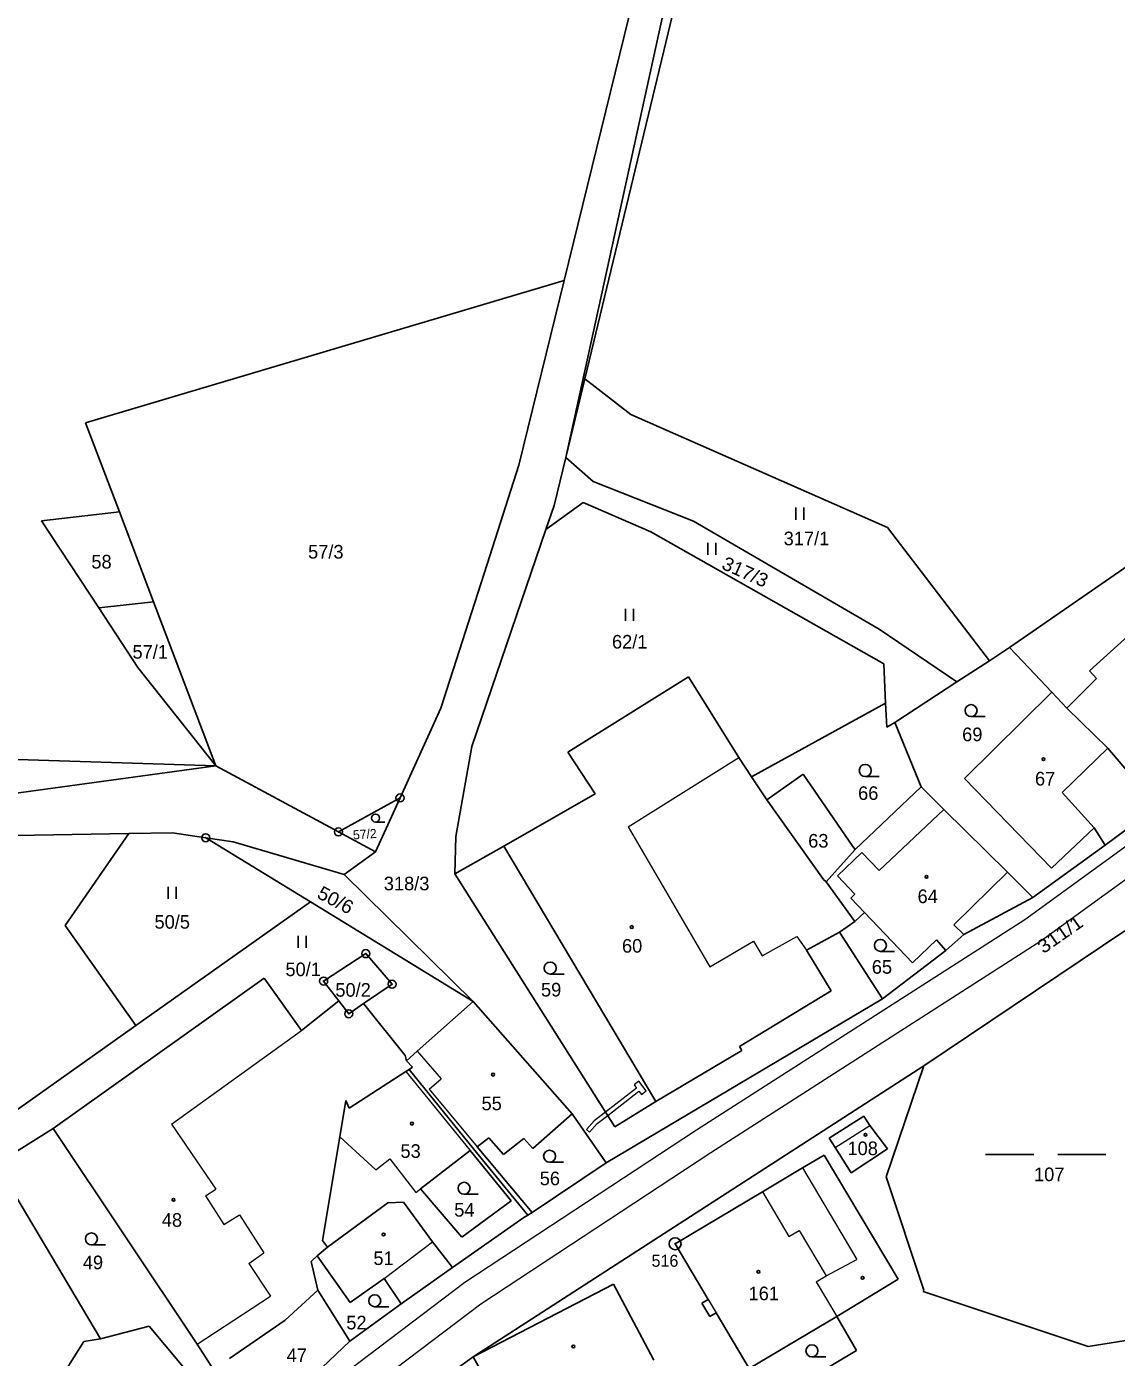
# Model space of a CAD drawing. Extents: x -633485 to -630509, y -1112692 to -1108818.
# Drawn here: x -631971.2 to -631835.2, y -1111718.1 to -1111552 of the extents above; entities that cross this region are included whole.
import ezdxf
from ezdxf.enums import TextEntityAlignment as Align

# ---------------------------------------------------------------- set-up
doc = ezdxf.new("R2010")
doc.units = 0
doc.header["$LTSCALE"] = 0.68
for name, color, linetype, lineweight in [('1', 7, 'Continuous', 25), ('13', 7, 'Continuous', 13), ('3', 7, 'Continuous', 25), ('4', 7, 'Continuous', 13), ('5', 7, 'Continuous', 25), ('8', 7, 'Continuous', 25)]:
    doc.layers.add(name, color=color, linetype=linetype, lineweight=lineweight)
doc.layers.add('2', color=7, linetype='Continuous')

msp = doc.modelspace()

# ---------------------------------------------------------------- linework, layer by layer
at = {"layer": '1'}
for p, q in [((-631901.53, -1111595.94), (-631843.85, -1111356.21)), ((-631904.1, -1111583.66), (-631892.04, -1111534.6)), ((-631903.91, -1111605.76), (-631890.19, -1111543.34)), ((-631963.83, -1111601.41), (-631904.1, -1111583.66)), ((-631909.75, -1111606.69), (-631904.1, -1111583.66)), ((-631903.91, -1111605.76), (-631901.53, -1111595.94)), ((-631901.53, -1111595.94), (-631895.78, -1111600.39)), ((-631895.78, -1111600.39), (-631863.75, -1111614.5)), ((-631963.83, -1111601.41), (-631959.6, -1111612.53)), ((-631905.36, -1111611.74), (-631903.91, -1111605.76)), ((-631903.91, -1111605.76), (-631900.48, -1111608.75)), ((-631913.72, -1111619.07), (-631909.75, -1111606.69)), ((-631900.48, -1111608.75), (-631887.96, -1111613.7)), ((-631848.51, -1111629.48), (-631819.16, -1111609.13)), ((-631969.34, -1111613.67), (-631959.6, -1111612.53)), ((-631959.6, -1111612.53), (-631955.34, -1111623.76)), ((-631906.38, -1111614.73), (-631901.71, -1111611.37)), ((-631906.38, -1111614.73), (-631905.36, -1111611.74)), ((-631901.71, -1111611.37), (-631893.28, -1111615.02)), ((-631969.34, -1111613.67), (-631962.2, -1111624.53)), ((-631887.96, -1111613.7), (-631864.8, -1111627.19)), ((-631915.61, -1111641.81), (-631906.38, -1111614.73)), ((-631893.28, -1111615.02), (-631864.21, -1111631.48)), ((-631863.75, -1111614.5), (-631851.01, -1111631.11)), ((-631919.48, -1111637.05), (-631913.72, -1111619.07)), ((-631962.2, -1111624.53), (-631955.34, -1111623.76)), ((-631955.34, -1111623.76), (-631947.56, -1111644.22)), ((-631962.2, -1111624.53), (-631957.33, -1111631.94)), ((-631855.07, -1111633.76), (-631864.8, -1111627.19)), ((-631851.01, -1111631.11), (-631848.51, -1111629.48)), ((-631848.51, -1111629.48), (-631846.09, -1111632.02)), ((-631957.33, -1111631.94), (-631947.56, -1111644.22)), ((-631864.21, -1111631.48), (-631864.01, -1111636.42)), ((-631855.07, -1111633.76), (-631851.01, -1111631.11)), ((-631846.09, -1111632.02), (-631843.21, -1111635.05)), ((-631903.66, -1111642.54), (-631888.57, -1111633.13)), ((-631888.57, -1111633.13), (-631882.28, -1111643.21)), ((-631862.83, -1111638.83), (-631855.07, -1111633.76)), ((-631854.12, -1111645.8), (-631843.21, -1111635.05)), ((-631843.21, -1111635.05), (-631841.34, -1111637.03)), ((-631924.59, -1111648.24), (-631919.48, -1111637.05)), ((-631880.7, -1111645.61), (-631864.01, -1111636.42)), ((-631864.01, -1111636.42), (-631863.82, -1111639.39)), ((-631841.34, -1111637.03), (-631836.24, -1111642.02)), ((-631863.82, -1111639.39), (-631862.83, -1111638.83)), ((-631862.83, -1111638.83), (-631859.52, -1111646.87)), ((-632001.91, -1111642.47), (-631947.56, -1111644.22)), ((-631917.62, -1111653.03), (-631915.61, -1111641.81)), ((-631903.66, -1111642.54), (-631900.21, -1111647.74)), ((-631836.24, -1111642.02), (-631832.24, -1111646.74)), ((-632001.49, -1111651.65), (-631947.56, -1111644.22)), ((-631947.56, -1111644.22), (-631932.27, -1111652.47)), ((-631882.28, -1111643.21), (-631880.7, -1111645.61)), ((-631880.7, -1111645.61), (-631878.81, -1111648.48)), ((-631878.81, -1111648.48), (-631874.25, -1111645.28)), ((-631874.25, -1111645.28), (-631868.07, -1111654.28)), ((-631854.12, -1111645.8), (-631843.25, -1111657)), ((-631867.79, -1111654.69), (-631859.52, -1111646.87)), ((-631859.52, -1111646.87), (-631856.69, -1111649.68)), ((-631932.27, -1111652.47), (-631924.59, -1111648.24)), ((-631927.66, -1111654.96), (-631924.59, -1111648.24)), ((-631911.64, -1111654.24), (-631900.21, -1111647.74)), ((-631878.81, -1111648.48), (-631871.74, -1111658.4)), ((-631856.69, -1111649.68), (-631848.78, -1111657.52)), ((-631836.57, -1111654.15), (-631830.18, -1111649.38)), ((-632000.57, -1111653.43), (-631958.43, -1111652.69)), ((-631966.4, -1111664.15), (-631958.43, -1111652.69)), ((-631958.43, -1111652.69), (-631952.97, -1111652.59)), ((-631952.97, -1111652.59), (-631948.84, -1111653.21)), ((-631932.27, -1111652.47), (-631927.66, -1111654.96)), ((-631843.25, -1111657), (-631837.93, -1111651.98)), ((-631837.93, -1111651.98), (-631836.57, -1111654.15)), ((-631935.78, -1111661.21), (-631948.84, -1111653.21)), ((-631948.84, -1111653.21), (-631945.4, -1111653.73)), ((-631945.4, -1111653.73), (-631931.58, -1111657.81)), ((-631917.74, -1111657.71), (-631917.62, -1111653.03)), ((-631917.74, -1111657.71), (-631911.64, -1111654.24)), ((-631911.64, -1111654.24), (-631892.66, -1111686.11)), ((-631868.07, -1111654.28), (-631867.79, -1111654.69)), ((-631845.59, -1111660.65), (-631836.57, -1111654.15)), ((-631931.58, -1111657.81), (-631927.66, -1111654.96)), ((-631871.39, -1111658.71), (-631867.79, -1111654.69)), ((-631848.78, -1111657.52), (-631845.59, -1111660.65)), ((-631931.58, -1111657.81), (-631915.46, -1111673.65)), ((-631917.74, -1111657.71), (-631900.34, -1111685.21)), ((-631871.74, -1111658.4), (-631871.39, -1111658.71)), ((-631871.39, -1111658.71), (-631867.81, -1111663.67)), ((-631854.23, -1111665.3), (-631845.59, -1111660.65)), ((-631935.78, -1111661.21), (-631957.55, -1111676.64)), ((-631915.46, -1111673.65), (-631935.78, -1111661.21)), ((-631867.81, -1111663.67), (-631866.6, -1111662.53)), ((-631866.6, -1111662.53), (-631860.64, -1111668.8)), ((-631957.55, -1111676.64), (-631966.4, -1111664.15)), ((-631869.75, -1111665), (-631867.81, -1111663.67)), ((-631873.85, -1111667.25), (-631869.75, -1111665)), ((-631869.75, -1111665), (-631864.38, -1111673.32)), ((-631860.64, -1111668.8), (-631857.63, -1111665.94)), ((-631859.21, -1111681.69), (-631834.1, -1111664.82)), ((-631857.63, -1111665.94), (-631856.44, -1111667.27)), ((-631856.44, -1111667.27), (-631854.23, -1111665.3)), ((-631873.85, -1111667.25), (-631870.79, -1111672.3)), ((-631864.38, -1111673.32), (-631856.44, -1111667.27)), ((-631934.12, -1111671.1), (-631928.87, -1111667.67)), ((-631928.87, -1111667.67), (-631925.58, -1111671.48)), ((-631967.87, -1111689.47), (-631941.54, -1111670.72)), ((-631941.54, -1111670.72), (-631936.89, -1111677.28)), ((-631934.12, -1111671.1), (-631932.21, -1111673.57)), ((-631929.13, -1111673.91), (-631925.58, -1111671.48)), ((-631882.23, -1111679.27), (-631870.79, -1111672.3)), ((-631936.89, -1111677.28), (-631932.21, -1111673.57)), ((-631932.21, -1111673.57), (-631930.98, -1111675.17)), ((-631930.98, -1111675.17), (-631929.13, -1111673.91)), ((-631929.13, -1111673.91), (-631923.96, -1111680.39)), ((-631922.43, -1111679.85), (-631915.46, -1111673.65)), ((-631915.46, -1111673.65), (-631903.08, -1111687.64)), ((-631898.86, -1111693.79), (-631864.38, -1111673.32)), ((-631957.55, -1111676.64), (-631977.11, -1111690.5)), ((-631882.23, -1111679.27), (-631881.94, -1111679.76)), ((-631923.96, -1111680.39), (-631923.77, -1111681.04)), ((-631923.77, -1111681.04), (-631922.43, -1111679.85)), ((-631892.66, -1111686.11), (-631881.94, -1111679.76)), ((-631930.95, -1111686.95), (-631923.85, -1111682.38)), ((-631923.85, -1111682.38), (-631923.44, -1111682.11)), ((-631923.77, -1111681.04), (-631923.02, -1111681.85)), ((-631923.44, -1111682.11), (-631923.02, -1111681.85)), ((-631923.44, -1111682.11), (-631915.43, -1111692.02)), ((-631915.46, -1111717.97), (-631859.21, -1111681.69)), ((-631863.89, -1111695.51), (-631859.21, -1111681.69)), ((-631900.34, -1111685.21), (-631897.77, -1111689.28)), ((-631932.12, -1111690.55), (-631931.36, -1111686.01)), ((-631931.36, -1111686.01), (-631930.95, -1111686.95)), ((-631897.77, -1111689.28), (-631892.66, -1111686.11)), ((-631908.01, -1111692), (-631903.08, -1111687.64)), ((-631903.08, -1111687.64), (-631898.86, -1111693.79)), ((-631871.01, -1111690.69), (-631866.68, -1111687.95)), ((-631866.68, -1111687.95), (-631865.94, -1111689.1)), ((-631865.94, -1111689.1), (-631863.73, -1111692.02)), ((-631974.95, -1111693.92), (-631967.87, -1111689.47)), ((-631967.87, -1111689.47), (-631949.92, -1111716.39)), ((-631934.27, -1111703.46), (-631932.12, -1111690.55)), ((-631914.97, -1111691.79), (-631913.51, -1111690.67)), ((-631913.51, -1111690.67), (-631911.69, -1111692.72)), ((-631911.69, -1111692.72), (-631909.14, -1111690.73)), ((-631909.14, -1111690.73), (-631908.01, -1111692)), ((-631871.01, -1111690.69), (-631870.28, -1111691.86)), ((-631922.02, -1111697.02), (-631915.83, -1111692.23)), ((-631915.83, -1111692.23), (-631910.71, -1111698.51)), ((-631915.43, -1111692.02), (-631908.64, -1111700.3)), ((-631914.97, -1111691.79), (-631908.09, -1111699.96)), ((-631870.28, -1111691.86), (-631868.26, -1111695.04)), ((-631868.26, -1111695.04), (-631863.73, -1111692.02)), ((-631974.95, -1111693.92), (-631965, -1111710.64)), ((-631908.09, -1111699.96), (-631898.86, -1111693.79)), ((-631874.35, -1111694.41), (-631871.64, -1111692.8)), ((-631871.64, -1111692.8), (-631862.42, -1111708.31)), ((-631879.35, -1111697.38), (-631874.35, -1111694.41)), ((-631863.89, -1111695.51), (-631859.2, -1111709.66)), ((-631922.02, -1111697.02), (-631916.88, -1111703.05)), ((-631890.26, -1111703.87), (-631879.35, -1111697.38)), ((-631933.63, -1111704.28), (-631926.11, -1111698.75)), ((-631926.11, -1111698.75), (-631924.17, -1111698.69)), ((-631924.17, -1111698.69), (-631920.53, -1111703.63)), ((-631916.88, -1111703.05), (-631910.71, -1111698.51)), ((-631918.02, -1111706.84), (-631909.13, -1111700.61)), ((-631909.13, -1111700.61), (-631908.64, -1111700.3)), ((-631908.64, -1111700.3), (-631908.09, -1111699.96)), ((-631934.27, -1111703.46), (-631933.63, -1111704.28)), ((-631920.53, -1111703.63), (-631918.02, -1111706.84)), ((-631890.26, -1111703.87), (-631886.13, -1111710.83)), ((-631935.67, -1111706.08), (-631934.91, -1111705.39)), ((-631934.91, -1111705.39), (-631933.63, -1111704.28)), ((-631934.91, -1111705.39), (-631930.8, -1111711.2)), ((-631935.67, -1111706.08), (-631934.84, -1111709.67)), ((-631924.44, -1111711.38), (-631918.02, -1111706.84)), ((-631930.8, -1111711.2), (-631926.55, -1111708.23)), ((-631926.55, -1111708.23), (-631924.44, -1111711.38)), ((-631915.46, -1111717.97), (-631897.93, -1111708.91)), ((-631897.93, -1111708.91), (-631892.89, -1111718.42)), ((-631870.08, -1111712.97), (-631862.42, -1111708.31)), ((-631965, -1111710.64), (-631961.97, -1111715.74)), ((-631938.92, -1111713.4), (-631934.84, -1111709.67)), ((-631934.84, -1111709.67), (-631930.86, -1111716.02)), ((-631859.29, -1111709.82), (-631859.2, -1111709.66)), ((-631859.29, -1111709.82), (-631838.71, -1111716.69)), ((-631930.86, -1111716.02), (-631924.44, -1111711.38)), ((-631886.9, -1111711.29), (-631886.13, -1111710.83)), ((-631886.9, -1111711.29), (-631885.92, -1111712.96)), ((-631945.88, -1111718.19), (-631938.92, -1111713.4)), ((-631885.92, -1111712.96), (-631885.14, -1111712.49)), ((-631885.14, -1111712.49), (-631881.01, -1111719.45)), ((-631881.01, -1111719.45), (-631870.08, -1111712.97)), ((-631870.08, -1111712.97), (-631867.59, -1111717.18)), ((-631964.04, -1111716.07), (-631961.97, -1111715.74)), ((-631961.97, -1111715.74), (-631955.91, -1111714.17)), ((-631955.91, -1111714.17), (-631949.96, -1111721.29)), ((-631838.71, -1111716.69), (-631832.42, -1111715.71)), ((-631974.18, -1111732.05), (-631964.04, -1111716.07)), ((-631949.92, -1111716.39), (-631947.83, -1111719.66)), ((-631939.82, -1111724.55), (-631930.86, -1111716.02)), ((-631878.44, -1111723.62), (-631867.59, -1111717.18)), ((-631917.89, -1111719.74), (-631915.46, -1111717.97)), ((-631915.46, -1111717.97), (-631911.4, -1111725.24))]:
    msp.add_line(p, q, dxfattribs=at)
at = {"layer": '13'}
msp.add_lwpolyline([(-631935.9, -1111727.56), (-631914.51, -1111711.36), (-631885.8, -1111692.49), (-631844.62, -1111666.09), (-631807.03, -1111638.81), (-631767.97, -1111614.41), (-631746.51, -1111599.55), (-631748.39, -1111596.83), (-631769.96, -1111611.77), (-631809.01, -1111636.17), (-631846.6, -1111663.43), (-631887.58, -1111689.71), (-631916.51, -1111708.73), (-631937.96, -1111724.98)], dxfattribs=at)
for points in [[(-631898.93, -1111687.44), (-631898.66, -1111687.87), (-631894.77, -1111684.84), (-631894.46, -1111685.23), (-631893.87, -1111684.77), (-631894.79, -1111683.59), (-631895.38, -1111684.05), (-631895.07, -1111684.44)], [(-631898.66, -1111687.87), (-631898.93, -1111687.44), (-631900.34, -1111688.54), (-631901.3, -1111689.6), (-631900.92, -1111689.94), (-631899.96, -1111688.88)]]:
    msp.add_lwpolyline(points, close=True, dxfattribs=at)
at = {"layer": '3'}
for p, q in [((-631875.171, -1111613.51), (-631875.171, -1111612.01)), ((-631874.17, -1111613.51), (-631874.17, -1111612.01)), ((-631886.171, -1111617.88), (-631886.171, -1111616.38)), ((-631885.17, -1111617.88), (-631885.17, -1111616.38)), ((-631896.441, -1111626.15), (-631896.441, -1111624.65)), ((-631895.44, -1111626.15), (-631895.44, -1111624.65)), ((-631853.313, -1111638.09), (-631851.563, -1111638.09)), ((-631866.523, -1111645.56), (-631864.773, -1111645.56)), ((-631927.645, -1111651.25), (-631926.473, -1111651.25)), ((-631953.541, -1111660.83), (-631953.541, -1111659.33)), ((-631952.54, -1111660.83), (-631952.54, -1111659.33)), ((-631937.291, -1111666.93), (-631937.291, -1111665.43)), ((-631936.29, -1111666.93), (-631936.29, -1111665.43)), ((-631864.633, -1111667.39), (-631862.883, -1111667.39)), ((-631905.843, -1111670.22), (-631904.093, -1111670.22)), ((-631905.913, -1111693.7), (-631904.163, -1111693.7)), ((-631851.489, -1111692.75), (-631845.489, -1111692.75)), ((-631842.489, -1111692.75), (-631836.489, -1111692.75)), ((-631916.593, -1111697.7), (-631914.843, -1111697.7)), ((-631963.113, -1111704.02), (-631961.363, -1111704.02)), ((-631927.743, -1111711.73), (-631925.993, -1111711.73)), ((-631873.173, -1111717.99), (-631871.423, -1111717.99))]:
    msp.add_line(p, q, dxfattribs=at)
for centre, radius in [((-631853.3129, -1111637.3398), 0.75), ((-631866.5229, -1111644.8098), 0.75), ((-631927.6452, -1111650.7474), 0.5025), ((-631864.6329, -1111666.6398), 0.75), ((-631905.8429, -1111669.4698), 0.75), ((-631905.9129, -1111692.9498), 0.75), ((-631916.5929, -1111696.9498), 0.75), ((-631963.1129, -1111703.2698), 0.75), ((-631927.7429, -1111710.9798), 0.75), ((-631873.1729, -1111717.2398), 0.75)]:
    msp.add_circle(centre, radius, dxfattribs=at)
at = {"layer": '4'}
for p, q in [((-631838.52, -1111632.36), (-631832.41, -1111626.84)), ((-631837.64, -1111633.33), (-631838.52, -1111632.36)), ((-631841.34, -1111637.03), (-631837.64, -1111633.33)), ((-631841.93, -1111647.54), (-631836.24, -1111642.02)), ((-631896.12, -1111651.85), (-631882.28, -1111643.21)), ((-631841.93, -1111647.54), (-631837.93, -1111651.98)), ((-631864.8, -1111657.3), (-631856.69, -1111649.68)), ((-631896.12, -1111651.85), (-631885.92, -1111669.31)), ((-631869.98, -1111657.95), (-631866.93, -1111655.06)), ((-631866.93, -1111655.06), (-631864.8, -1111657.3)), ((-631855.46, -1111664.07), (-631848.78, -1111657.52)), ((-631869.98, -1111657.95), (-631867.8, -1111660.24)), ((-631868.31, -1111660.73), (-631867.8, -1111660.24)), ((-631868.31, -1111660.73), (-631866.6, -1111662.53)), ((-631855.46, -1111664.07), (-631854.23, -1111665.3)), ((-631879.38, -1111667.94), (-631875.05, -1111665.51)), ((-631875.05, -1111665.51), (-631873.85, -1111667.25)), ((-631885.92, -1111669.31), (-631880.46, -1111666.13)), ((-631880.46, -1111666.13), (-631879.38, -1111667.94)), ((-631953.12, -1111688.94), (-631936.89, -1111677.28)), ((-631922.43, -1111679.85), (-631919.46, -1111683.28)), ((-631923.85, -1111682.38), (-631915.83, -1111692.23)), ((-631920.97, -1111684.58), (-631919.46, -1111683.28)), ((-631920.97, -1111684.58), (-631914.97, -1111691.79)), ((-631953.12, -1111688.94), (-631947.59, -1111697.07)), ((-631870.28, -1111691.86), (-631865.94, -1111689.1)), ((-631932.12, -1111690.55), (-631927.6, -1111694.65)), ((-631927.6, -1111694.65), (-631925.84, -1111693.29)), ((-631925.84, -1111693.29), (-631922.6, -1111697.47)), ((-631874.35, -1111694.41), (-631867.57, -1111705.82)), ((-631948.87, -1111697.89), (-631947.59, -1111697.07)), ((-631922.6, -1111697.47), (-631922.02, -1111697.02)), ((-631879.35, -1111697.38), (-631876.04, -1111702.96)), ((-631948.87, -1111697.89), (-631946.56, -1111701.48)), ((-631946.56, -1111701.48), (-631944.64, -1111700.25)), ((-631944.64, -1111700.25), (-631941.57, -1111705.02)), ((-631876.04, -1111702.96), (-631874.78, -1111702.21)), ((-631874.78, -1111702.21), (-631871.4, -1111707.89)), ((-631926.55, -1111708.23), (-631920.53, -1111703.63)), ((-631943.47, -1111706.34), (-631941.57, -1111705.02)), ((-631871.4, -1111707.89), (-631867.57, -1111705.82)), ((-631943.47, -1111706.34), (-631940.74, -1111710.4)), ((-631872.66, -1111708.64), (-631871.4, -1111707.89)), ((-631872.66, -1111708.64), (-631870.08, -1111712.97)), ((-631949.92, -1111716.39), (-631940.74, -1111710.4)), ((-631886.13, -1111710.83), (-631885.14, -1111712.49))]:
    msp.add_line(p, q, dxfattribs=at)
at = {"layer": '5'}
for centre in [(-631844.2768, -1111643.4092), (-631858.8668, -1111658.0892), (-631895.6668, -1111664.3492), (-631912.9768, -1111682.7692), (-631923.0968, -1111688.8792), (-631866.4868, -1111690.2692), (-631952.8568, -1111698.3892), (-631926.6368, -1111702.7192), (-631879.8568, -1111707.3692), (-631866.8468, -1111708.1292), (-631902.9468, -1111716.6892)]:
    msp.add_circle(centre, 0.175, dxfattribs=at)
at = {"layer": '8'}
for centre, radius in [((-631924.59, -1111648.2399), 0.5), ((-631924.59, -1111648.2399), 0.0303), ((-631932.27, -1111652.4699), 0.5), ((-631932.27, -1111652.4699), 0.0303), ((-631948.84, -1111653.2099), 0.5), ((-631948.84, -1111653.2099), 0.0303), ((-631928.87, -1111667.6699), 0.5), ((-631928.87, -1111667.6699), 0.0303), ((-631934.12, -1111671.0999), 0.5), ((-631934.12, -1111671.0999), 0.0303), ((-631925.58, -1111671.4799), 0.5), ((-631925.58, -1111671.4799), 0.0303), ((-631930.98, -1111675.1699), 0.5), ((-631930.98, -1111675.1699), 0.0303), ((-631890.26, -1111703.8698), 0.75), ((-631890.26, -1111703.8698), 0.03)]:
    msp.add_circle(centre, radius, dxfattribs=at)

# ---------------------------------------------------------------- texts
at = {"layer": '2'}
for s, p in [('317/1', (-631876.7, -1111616.705)), ('57/3', (-631936.06, -1111618.365)), ('58', (-631963.11, -1111619.605)), ('57/1', (-631957.98, -1111630.855)), ('62/1', (-631898.13, -1111629.595)), ('69', (-631854.42, -1111641.155)), ('67', (-631845.33, -1111646.685)), ('66', (-631867.41, -1111648.485)), ('63', (-631873.64, -1111654.435)), ('318/3', (-631926.61, -1111659.765)), ('64', (-631859.99, -1111661.365)), ('60', (-631896.88, -1111667.545)), ('50/1', (-631938.89, -1111670.475)), ('65', (-631865.7, -1111670.175)), ('50/2', (-631932.66, -1111673.045)), ('59', (-631906.99, -1111673.015)), ('55', (-631914.41, -1111687.215)), ('53', (-631924.53, -1111693.155)), ('56', (-631907.15, -1111696.575)), ('107', (-631845.45, -1111696.065)), ('54', (-631917.82, -1111700.485)), ('48', (-631954.32, -1111701.755)), ('49', (-631964.18, -1111707.055)), ('51', (-631927.91, -1111706.525)), ('161', (-631881.08, -1111710.925)), ('52', (-631931.29, -1111714.565)), ('47', (-631938.74, -1111718.645))]:
    msp.add_text(s, height=1.7, dxfattribs=at).set_placement(p)
for s, rotation, width, p in [('317/3', 336, 1.05, (-631884.572, -1111619.588)), ('311/1', 35, 1.1, (-631844.276, -1111667.738))]:
    msp.add_text(s, height=1.7, rotation=rotation, dxfattribs=dict(at, width=width)).set_placement(p)
msp.add_text('57/2', height=1.139, rotation=4, dxfattribs=at).set_placement((-631930.42, -1111653.424))
at = {"layer": '2', "width": 1.05}
msp.add_text('50/6', height=1.7, rotation=332, dxfattribs=at).set_placement((-631933.0281, -1111661.7307), align=Align.CENTER)
at = {"layer": '2'}
for s, p in [('50/5', (-631953.019, -1111664.552)), ('108', (-631866.839, -1111692.815))]:
    msp.add_text(s, height=1.7, dxfattribs=at).set_placement(p, align=Align.CENTER)
at = {"layer": '8'}
msp.add_text('516', height=1.5, dxfattribs=at).set_placement((-631893.19, -1111706.745))

doc.saveas('drawing.dxf')
